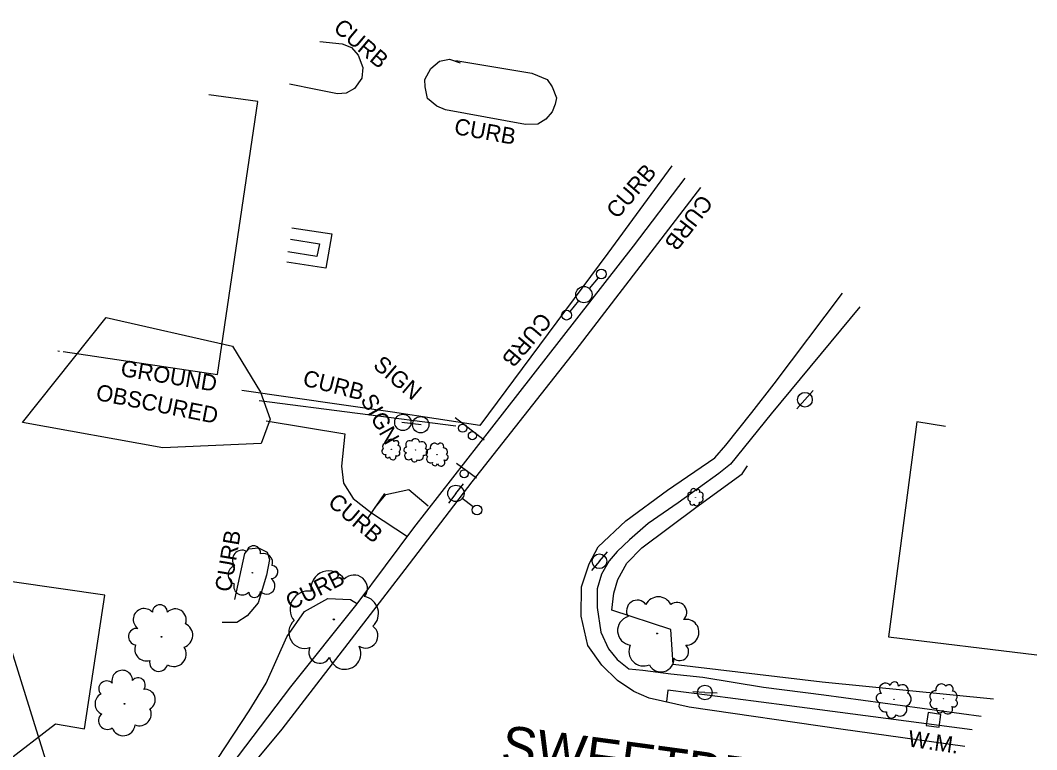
# Model space of a CAD drawing. Extents: x 1722896 to 1754269, y 648279 to 666297.
# Drawn here: x 1730744.7 to 1731056.3, y 653507.8 to 653731.5 of the extents above; entities that cross this region are included whole.
import ezdxf

# ---------------------------------------------------------------- set-up
doc = ezdxf.new("R2010")
doc.units = 0
for name, color, linetype in [('DESIGN - CENTERLINE - Proposed Text', 7, 'Continuous'), ('DESIGN - CONTOURS - Intermediate with optional Text', 7, 'Continuous'), ('DESIGN - PUBLIC HEARING - Shapes', 7, 'Continuous'), ('DESIGN - SCRATCH - User 1', 7, 'Continuous'), ('DESIGN - SHEET - Linework', 7, 'Continuous'), ('SURVEY - CENTERLINE - Preliminary', 7, 'Continuous'), ('SURVEY - CENTERLINE - Preliminary Text', 7, 'Continuous'), ('SURVEY - DTM - Breaklines', 7, 'Continuous'), ('SURVEY - VEGETATION - Features with Text', 7, 'Continuous')]:
    doc.layers.add(name, color=color, linetype=linetype)

msp = doc.modelspace()

# ---------------------------------------------------------------- linework, layer by layer
at = {"layer": 'DESIGN - CENTERLINE - Proposed Text'}
for points in [[(1730757.89, 653629.85), (1730805.2, 653622.81), (1730817.57, 653706.51), (1730802.56, 653708.63)], [(1730827.95, 653667.78), (1730840.27, 653665.99), (1730838.36, 653655.47), (1730826.38, 653657.33)], [(1730827.53, 653664.36), (1730836.4, 653662.91), (1730835.58, 653659.07), (1730826.76, 653660.47)], [(1730756.24, 653630.1), (1730756.74, 653630.02)], [(1731028.39, 653606.87), (1731019.59, 653608.34), (1731010.86, 653542.36), (1731056.32, 653536.83)], [(1730681.32, 653522.74), (1730673.19, 653465.69), (1730685.95, 653463.92), (1730685.86, 653461.96), (1730732.77, 653455.13), (1730739.9, 653503.63), (1730755.54, 653515.73), (1730764.39, 653514.21), (1730770.59, 653555.15), (1730715.14, 653563.12)]]:
    msp.add_lwpolyline(points, dxfattribs=at)
at = {"layer": 'DESIGN - CONTOURS - Intermediate with optional Text'}
msp.add_line((1731024.71, 653516.92), (1731024.71, 653516.92), dxfattribs=at)
msp.add_lwpolyline([(1731023.02, 653519.19), (1731022.44, 653515.23), (1731026.39, 653514.65), (1731026.98, 653518.6), (1731023.02, 653519.19)], dxfattribs=at)
at = {"layer": 'DESIGN - PUBLIC HEARING - Shapes'}
for p, q in [((1730861.73, 653608.27), (1730867.6, 653607.49)), ((1730861.99, 653608.14), (1730861.99, 653608.14)), ((1730867.46, 653607.42), (1730867.46, 653607.42)), ((1730878.07, 653609.67), (1730886.94, 653602.84)), ((1730878.49, 653595.62), (1730884.53, 653591.17))]:
    msp.add_line(p, q, dxfattribs=at)
for centre, radius in [((1730861.99, 653608.16), 2.5), ((1730867.46, 653607.44), 2.5), ((1730880.35, 653606.37), 1.25), ((1730883.32, 653604.08), 1.25), ((1730880.8, 653592.4), 1.25)]:
    msp.add_circle(centre, radius, dxfattribs=at)
at = {"layer": 'DESIGN - SCRATCH - User 1'}
msp.add_lwpolyline([(1730817.95, 653614.86), (1730878.23, 653607.05)], dxfattribs=at)
at = {"layer": 'SURVEY - CENTERLINE - Preliminary'}
for points in [[(1730771.05, 653640.28), (1730809.79, 653631.55), (1730818.32, 653617.38), (1730821.33, 653609.09), (1730818.59, 653601.65), (1730788.4, 653600.38), (1730745.35, 653608.1), (1730771.05, 653640.28)], [(1730561.68, 653361.84), (1730609.84, 653355.5), (1730660.14, 653350.65), (1730676.67, 653356.21), (1730698.91, 653381.55), (1730702.27, 653415.46), (1730726.55, 653409.9), (1730777.18, 653472.65), (1730755.43, 653495.39), (1730728.31, 653582.2), (1730726.86, 653583.43), (1730667.72, 653502.49), (1730610.68, 653426.08), (1730561.68, 653361.84)]]:
    msp.add_lwpolyline(points, dxfattribs=at)
at = {"layer": 'SURVEY - CENTERLINE - Preliminary Text'}
for points in [[(1730836.52, 653724.98), (1730843.41, 653724.25), (1730846.23, 653723.12), (1730848.31, 653720.75), (1730849.68, 653717), (1730849.45, 653713.72), (1730847.17, 653710.53), (1730844.64, 653709.1), (1730841.94, 653708.87), (1730835.27, 653710.2), (1730827.23, 653711.9)], [(1730878.2, 653719.16), (1730901.56, 653715.24), (1730906.21, 653713.27), (1730907.82, 653711.04), (1730909.12, 653707.67), (1730908.7, 653705.76), (1730907.73, 653703.34), (1730905.85, 653701.1), (1730903.33, 653699.63), (1730899.6, 653699.52), (1730875.04, 653704.03), (1730872.38, 653705.16), (1730869.6, 653707.51), (1730868.83, 653711.07), (1730868.71, 653713.34), (1730870.6, 653716.66), (1730873.2, 653718.93), (1730876.3, 653719.54), (1730879.53, 653718.45)], [(1730944.5, 653686.83), (1730924.84, 653660.06), (1730885.62, 653607.2), (1730858.83, 653611.28), (1730812.58, 653617.92)], [(1730648.73, 653351.04), (1730664.92, 653349.59), (1730673.61, 653351.73), (1730680.23, 653355.39), (1730686.61, 653361.56), (1730697.12, 653372.09), (1730724.01, 653401.45), (1730739.26, 653418.97), (1730785.41, 653472.26), (1730804.51, 653496.63), (1730827.6, 653527.08), (1730847.97, 653552.56), (1730865.38, 653575.82), (1730893.28, 653611.62), (1730932.68, 653662.19), (1730948.54, 653683.03)], [(1730953.24, 653680.22), (1730914.98, 653630.43), (1730883.12, 653589.92), (1730862.56, 653563.07), (1730824.93, 653514.04), (1730726.47, 653395.81), (1730683.99, 653351.19), (1730678.54, 653347.6), (1730671.71, 653345.55), (1730665.12, 653344), (1730655.42, 653344.62), (1730639.11, 653347.27), (1730562.92, 653359.51)], [(1731034.33, 653508.73), (1730996.31, 653514.05), (1730949.75, 653520.84), (1730937.56, 653523.54), (1730932.81, 653525.6), (1730927.76, 653528.98), (1730922.96, 653533.73), (1730918.72, 653539.7), (1730916.63, 653548.75), (1730916.8, 653557.74), (1730919.07, 653564.79), (1730921.83, 653570.02), (1730930.34, 653577.99), (1730943.1, 653587.32), (1730957.66, 653597.33), (1730960.97, 653601.16), (1730968.98, 653611.16), (1730975.8, 653620.02), (1730996.77, 653647.81)], [(1731002.08, 653643.62), (1730974.87, 653610.82), (1730962.45, 653595.29), (1730958.88, 653592.49), (1730946.4, 653583.53), (1730937.19, 653577.1), (1730931.47, 653572.15), (1730927.71, 653568.6), (1730925.24, 653565.67), (1730922.88, 653561.59), (1730921.57, 653557.16), (1730921.57, 653551.4), (1730922.69, 653543.86), (1730925.03, 653538.72), (1730927.68, 653535.4), (1730931.29, 653532.54), (1730935.53, 653532.16), (1730944.14, 653531.02), (1730953.95, 653530.06), (1730972.58, 653526.96), (1730991.04, 653524.64), (1731039.3, 653518.06)], [(1730820.09, 653608.59), (1730844.18, 653604.62), (1730843.18, 653594.76), (1730843.84, 653589.55), (1730846.76, 653584.84), (1730852.43, 653580.41), (1730863.44, 653573.16)], [(1731043.08, 653523.27), (1730990.59, 653528.53), (1730944.92, 653533.95), (1730944.2, 653544.62), (1730926.08, 653550.61), (1730926.71, 653555.82), (1730927.87, 653559.97), (1730930.65, 653564.94), (1730935.23, 653569.67), (1730951.78, 653582.03), (1730966.06, 653592.41), (1730967.62, 653594.79)], [(1730810.52, 653553.81), (1730813.52, 653567.91), (1730814.82, 653569.37), (1730817.7, 653569.72), (1730820.35, 653568.4), (1730821.14, 653566.06), (1730820.19, 653561.3), (1730817.64, 653552.78), (1730814.25, 653548.8), (1730811.05, 653546.75), (1730806.55, 653546.8)], [(1730767.21, 653456.7), (1730781.57, 653473.25), (1730792.46, 653487.13), (1730805.28, 653505.03), (1730814.88, 653519.72), (1730820.07, 653528.16), (1730826.45, 653542.36), (1730831.8, 653550.14), (1730839.02, 653554.13), (1730845.96, 653553.87), (1730848.04, 653552.5)], [(1731036.49, 653513.83), (1730979.75, 653521.37), (1730956.12, 653524.44), (1730943.22, 653526.08), (1730942.83, 653522.54)]]:
    msp.add_lwpolyline(points, dxfattribs=at)
at = {"layer": 'SURVEY - DTM - Breaklines'}
for p, q in [((1730921.85, 653652.5), (1730919.11, 653649.25)), ((1730915.89, 653645.43), (1730913.15, 653642.18)), ((1730985.28, 653615.1), (1730987.75, 653617.93)), ((1730985.28, 653615.1), (1730982.81, 653612.28)), ((1730878.25, 653586.37), (1730880.56, 653589.32)), ((1730878.25, 653586.37), (1730875.94, 653583.41)), ((1730883.57, 653582.21), (1730880.22, 653584.83)), ((1730922.27, 653565.57), (1730924.69, 653568.43)), ((1730922.27, 653565.57), (1730919.85, 653562.7)), ((1730954.59, 653525.32), (1730950.85, 653525.48)), ((1730954.59, 653525.32), (1730958.34, 653525.17))]:
    msp.add_line(p, q, dxfattribs=at)
for centre, radius in [((1730922.82, 653653.64), 1.5), ((1730917.5, 653647.34), 2.5), ((1730912.18, 653641.04), 1.5), ((1730985.28, 653615.1), 2.25), ((1730878.25, 653586.37), 2.5), ((1730884.75, 653581.29), 1.5), ((1730922.27, 653565.57), 2.25), ((1730954.59, 653525.32), 2.25)]:
    msp.add_circle(centre, radius, dxfattribs=at)
at = {"layer": 'SURVEY - VEGETATION - Features with Text'}
for points in [[(1730856.35, 653586.37), (1730851.25, 653578.91)], [(1730853.36, 653581.96), (1730856.8, 653586.04), (1730863.86, 653587.54), (1730869.8, 653582.54)]]:
    msp.add_lwpolyline(points, dxfattribs=at)
for centre, radius in [((1730858.45, 653599.89), 0.0351), ((1730865.83, 653599.65), 0.0423), ((1730872.44, 653598.26), 0.0414), ((1730951.73, 653585.19), 0.0297), ((1730815.85, 653562.05), 0.0912), ((1730840.83, 653547.74), 0.171), ((1730788, 653542.37), 0.117), ((1730939.94, 653543.41), 0.138), ((1731012.61, 653523.21), 0.0642), ((1731027.77, 653523.38), 0.0528), ((1730776.66, 653521.84), 0.111)]:
    msp.add_circle(centre, radius, dxfattribs=at)
for centre, radius, start, end in [((1730856.92, 653600.69), 1.15, 74.8655, 212.3897), ((1730858.35, 653601.83), 1.14, 25.7613, 181.5998), ((1730859.93, 653601.69), 0.839, 316.0142, 131.0145), ((1730860.21, 653600.08), 1.08, 305.8553, 72.701), ((1730864.09, 653601.33), 1.21, 63.7829, 220.5718), ((1730865.82, 653601.74), 1.38, 12.8357, 150.3599), ((1730867.85, 653600.85), 1.37, 323.7315, 119.57), ((1730871.71, 653600.44), 1.34, 41.6334, 197.4719), ((1730873.54, 653600.79), 0.99, 331.8863, 146.8866), ((1730856.54, 653599.27), 1.01, 125.8127, 282.6017), ((1730857.34, 653597.92), 0.69, 147.9289, 326.6745), ((1730858.91, 653597.68), 1, 187.9496, 21.3693), ((1730860.33, 653598.63), 0.763, 230.5683, 47.8874), ((1730863.11, 653599.71), 0.833, 85.8991, 264.6447), ((1730863.74, 653597.91), 1.21, 125.9198, 319.3395), ((1730867.03, 653597.88), 1.31, 243.8255, 10.6712), ((1730868.59, 653599.09), 1.01, 253.9844, 68.9847), ((1730870.44, 653598.68), 1.35, 90.7376, 228.2618), ((1730874.38, 653599.05), 1.28, 321.7274, 88.5731), ((1730874.99, 653597.45), 0.901, 246.4403, 63.7595), ((1730865.56, 653596.93), 0.921, 168.5384, 345.8576), ((1730870.48, 653596.94), 1.19, 141.6848, 298.4738), ((1730871.82, 653595.67), 0.814, 163.801, 342.5466), ((1730873.68, 653595.91), 1.18, 203.8217, 37.2414), ((1730950.27, 653584.85), 0.915, 132.7927, 259.6384), ((1730950.02, 653586.05), 0.646, 57.5057, 234.8248), ((1730951.11, 653586.99), 0.848, 14.887, 208.3067), ((1730952.46, 653586.95), 0.584, 334.8663, 153.6119), ((1730953.1, 653584.67), 0.969, 261.8029, 39.3271), ((1730953.27, 653585.9), 0.85, 312.7502, 109.5391), ((1730950.67, 653583.52), 0.71, 142.9516, 317.9519), ((1730952.01, 653583.57), 0.962, 212.6987, 8.5372), ((1730816.22, 653568.11), 2.18, 351.8999, 166.9002), ((1730812.69, 653566), 2.96, 61.647, 217.4855), ((1730819.27, 653565.13), 2.81, 341.741, 108.5866), ((1730811.39, 653561.41), 2.98, 110.7511, 248.2754), ((1730821.73, 653562.28), 1.99, 266.4539, 83.7731), ((1730839.34, 653557.1), 5.54, 31.9897, 187.8281), ((1730847.04, 653557.26), 4.09, 322.2426, 137.2428), ((1730812.78, 653557.83), 2.61, 161.6984, 318.4873), ((1730820.2, 653558.1), 2.61, 223.8352, 57.2549), ((1730816.52, 653556.22), 1.79, 183.8146, 2.5602), ((1730832.99, 653550.84), 5.58, 81.0938, 218.6181), ((1730849.26, 653549.59), 5.27, 312.0837, 78.9293), ((1730940.34, 653550.39), 4.27, 26.4709, 153.3165), ((1730782.67, 653547.71), 3.35, 40.9735, 234.3932), ((1730787.51, 653549.9), 2.31, 0.9528, 179.6985), ((1730933.87, 653550.33), 3.31, 36.6298, 211.6301), ((1730946.03, 653549.93), 3.01, 311.1838, 128.503), ((1730792.22, 653547.59), 3.36, 338.8367, 135.6256), ((1730932.32, 653544.29), 4.49, 106.3769, 262.2154), ((1730780.43, 653542.45), 2.55, 83.5922, 260.9113), ((1730793.76, 653542.9), 3.83, 287.8894, 65.4136), ((1730831.92, 653543.73), 4.89, 132.0411, 288.83), ((1730850.61, 653542.67), 3.72, 236.7966, 54.1157), ((1730948.83, 653543.8), 3.96, 268.5652, 101.9848), ((1730783.4, 653538.63), 3.62, 158.8792, 285.7249), ((1730791.81, 653537.09), 3.8, 238.7852, 34.6237), ((1730836.52, 653537.63), 3.36, 154.1572, 332.9029), ((1730844.25, 653537.3), 4.88, 194.1779, 27.5976), ((1730935.82, 653537.97), 4.52, 155.4811, 293.0053), ((1730946.89, 653537.84), 2.72, 228.5445, 47.2901), ((1730941.13, 653535.58), 3.96, 206.4283, 3.2172), ((1730787.14, 653534.61), 2.81, 169.0381, 344.0384), ((1730775.97, 653528.96), 3.18, 1.5925, 195.0122), ((1730780.84, 653527.65), 2.19, 321.5718, 140.3175), ((1730771.16, 653526.45), 2.42, 44.2112, 221.5303), ((1730782.9, 653523.12), 3.19, 299.4557, 96.2446), ((1731009.95, 653526.37), 1.84, 36.2315, 229.6512), ((1731012.69, 653527.34), 1.26, 356.2108, 174.9565), ((1731015.15, 653525.87), 1.84, 334.0947, 130.8836), ((1731027.11, 653526.23), 1.71, 35.9262, 191.7647), ((1731029.48, 653526.44), 1.26, 326.1791, 141.1794), ((1730771.04, 653521.86), 3.43, 119.4982, 246.3439), ((1731008.49, 653523.6), 1.4, 78.8502, 256.1693), ((1731015.78, 653523.24), 2.1, 283.1474, 60.6717), ((1731025.28, 653524.16), 1.72, 85.0304, 222.5546), ((1731025.1, 653521.95), 1.51, 135.9777, 292.7666), ((1731030.89, 653522.02), 1.15, 240.7332, 58.0523), ((1731030.33, 653524.13), 1.63, 316.0202, 82.8659), ((1730781.21, 653518.75), 3.63, 248.5084, 26.0326), ((1731009.94, 653521.37), 1.98, 154.1372, 280.9829), ((1731014.45, 653520.16), 2.08, 234.0433, 29.8817), ((1731026.65, 653520.17), 1.04, 158.0938, 336.8395), ((1731029.04, 653520.23), 1.51, 198.1145, 31.5342), ((1730771.36, 653516.66), 2.66, 129.6571, 304.6574), ((1731011.79, 653519.01), 1.54, 164.2962, 339.2964), ((1730776.28, 653515.67), 3.61, 199.4042, 355.2427)]:
    msp.add_arc(centre, radius, start, end, dxfattribs=at)

# ---------------------------------------------------------------- texts
at = {"layer": 'DESIGN - CONTOURS - Intermediate with optional Text'}
msp.add_text('W.M.', height=5, rotation=351.5463, dxfattribs=at).set_placement((1731016.63, 653508.82))
at = {"layer": 'DESIGN - PUBLIC HEARING - Shapes'}
for rotation, p in [(319.7959, (1730852.57, 653625.21)), (299.3048, (1730848.84, 653615.12))]:
    msp.add_text('SIGN', height=5, rotation=rotation, dxfattribs=at).set_placement(p)
at = {"layer": 'DESIGN - SCRATCH - User 1'}
for rotation, p in [(319.851, (1730840.38, 653728.56)), (349.8269, (1730877.48, 653696.61)), (49.4178, (1730927.72, 653670.29)), (232.5555, (1730953.43, 653678.38)), (229.852, (1730904.25, 653642.26)), (345.834, (1730831, 653619.53)), (319.7929, (1730838.68, 653583.07)), (80.5484, (1730809.25, 653555.94)), (26.4384, (1730827.65, 653550.49))]:
    msp.add_text('CURB', height=5, rotation=rotation, dxfattribs=at).set_placement(p)
at = {"layer": 'DESIGN - SHEET - Linework'}
msp.add_text('SWEETBRIAR AVE.', height=12, rotation=352.3153, dxfattribs=at).set_placement((1730891.66, 653503.49))
at = {"layer": 'SURVEY - VEGETATION - Features with Text'}
for s, rotation, p in [('GROUND', 350.5518, (1730775.23, 653622.43)), ('OBSCURED', 348.7645, (1730767.62, 653615.08))]:
    msp.add_text(s, height=5, rotation=rotation, dxfattribs=at).set_placement(p)

doc.saveas('drawing.dxf')
